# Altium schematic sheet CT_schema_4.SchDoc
size 368 x 207 mm
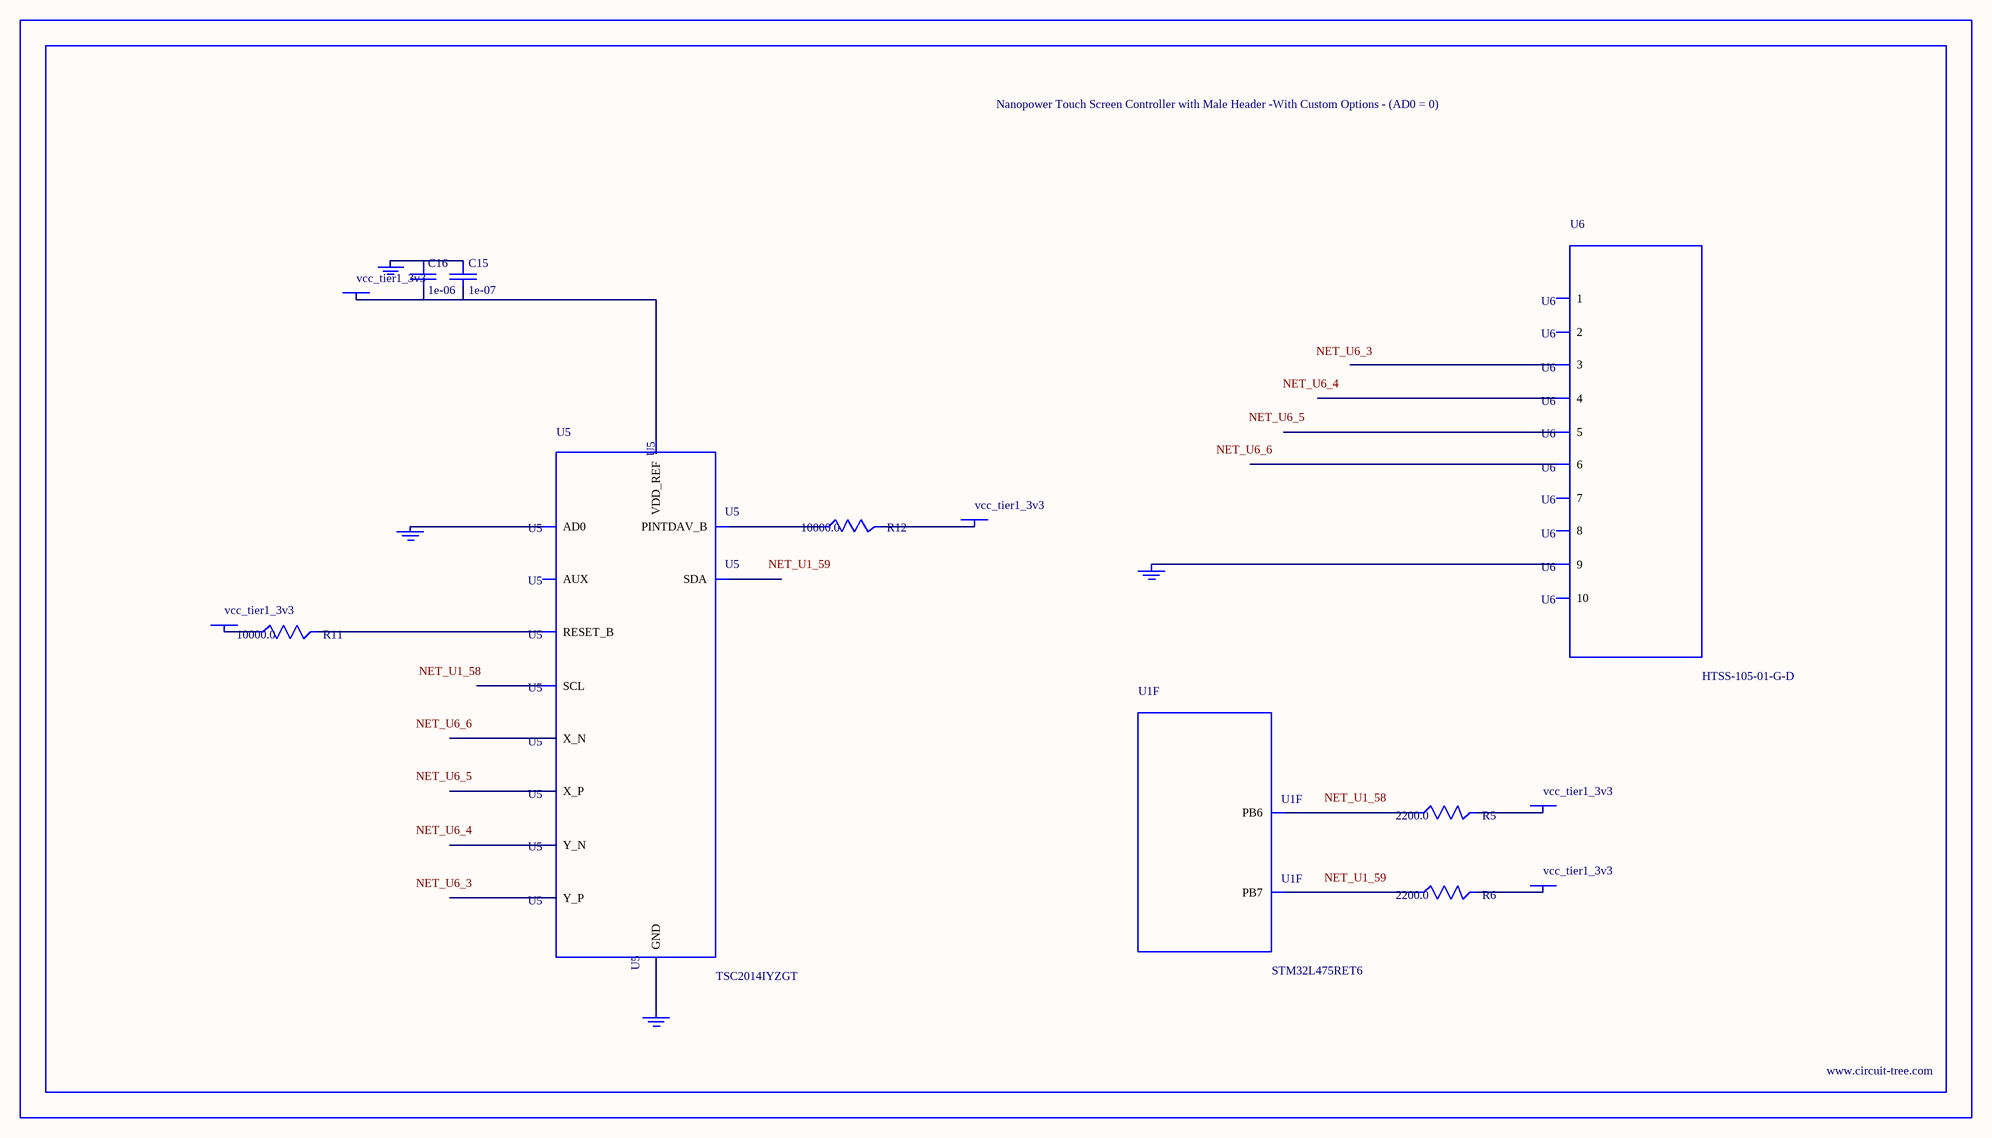
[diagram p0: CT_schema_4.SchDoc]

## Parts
BORDER3  (no value)
C15  1e-07  [C0402]
C16  1e-06  [C0603]
GND_INSTANCE_3_0  (no value)
GND_INSTANCE_3_1  (no value)
GND_INSTANCE_3_2  (no value)
GND_INSTANCE_3_3  (no value)
POWER_INSTANCE_3_0  vcc_tier1_3v3
POWER_INSTANCE_3_1  vcc_tier1_3v3
POWER_INSTANCE_3_2  vcc_tier1_3v3
POWER_INSTANCE_3_3  vcc_tier1_3v3
POWER_INSTANCE_3_4  vcc_tier1_3v3
R5  2200.0  [R0603]
R6  2200.0  [R0603]
R11  10000.0  [R0603]
R12  10000.0  [R0603]
U1  STM32L475RET6  [LQFP64]  (part F of 8)
U5  TSC2014IYZGT  [TSC2014IYZGT]
U6  HTSS-105-01-G-D  [HTSS-105-01-G-D]

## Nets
NetC15_1: C15.1 C16.1 GND_INSTANCE_3_0.0(GND)
NetC15_2: C15.2 C16.2 POWER_INSTANCE_3_2.0(PWR) U5.A2(VDD_REF)
NetGND_INSTANCE_3_1_0: GND_INSTANCE_3_1.0(GND) U5.B2(AD0)
NetGND_INSTANCE_3_2_0: GND_INSTANCE_3_2.0(GND) U5.D2(GND)
NetGND_INSTANCE_3_3_0: GND_INSTANCE_3_3.0(GND) U6.9
NetPOWER_INSTANCE_3_0_0: POWER_INSTANCE_3_0.0(PWR) R11.1
NetPOWER_INSTANCE_3_1_0: POWER_INSTANCE_3_1.0(PWR) R12.2
NetPOWER_INSTANCE_3_3_0: POWER_INSTANCE_3_3.0(PWR) R5.2
NetPOWER_INSTANCE_3_4_0: POWER_INSTANCE_3_4.0(PWR) R6.2
NetR5_1: R5.1 U1.58(PB6)
NetR6_1: R6.1 U1.59(PB7)
NetR11_2: R11.2 U5.C2(RESET_B)
NetR12_1: R12.1 U5.B1(PINTDAV_B)

Not connected (* = marked no-connect by the designer): U5 A1(AUX) A3(X_P) B3(Y_P) C1(SDA) C3(X_N) D1(SCL) D3(Y_N); U6 1 2 3 4 5 6 7 8 10

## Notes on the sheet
- Labels drawn without touching a wire or pin: NET_U1_58, NET_U1_59, NET_U6_3, NET_U6_4, NET_U6_5, NET_U6_6

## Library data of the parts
BORDER3 = BORDER_PAGE3
C15 = C0402C104K3RACTU
C16 = C0603C105K3RACTU
GND_INSTANCE_3_0-GND_INSTANCE_3_3 = GND
POWER_INSTANCE_3_0-POWER_INSTANCE_3_4 = PWR
R5 R6 = RC0603JR-072K2L
R11 R12 = RC0603JR-0710KL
